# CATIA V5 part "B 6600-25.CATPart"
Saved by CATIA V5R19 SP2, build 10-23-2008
Part number: B 6600-25
Bounding box of the stored display mesh (mm): x -59.975 to 59.975, y -59.975 to 59.975, z 0 to 190
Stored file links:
  C:\Users\Bora\Desktop\3D Katı model\B serisi\B 6600\B 6600-25.CATPart
  C:\Program Files\Dassault Systemes\B19\intel_a\reffiles\standard\MetricThickPitch.txt
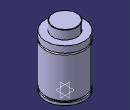
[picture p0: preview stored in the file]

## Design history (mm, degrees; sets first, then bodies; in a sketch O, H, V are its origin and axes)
Body1 (main body)
  Sketch1 on yz-plane, origin (0, 0, 0), H (0, 1, 0), V (0, 0, 1)
    point P3 (37.5, 189)
    point P5 (37.5, 189)
    point P10 (60, 137)
    point P11 (60, 142)
    point P13 (60, 142)
    point P14 (60, 137)
    line L1 (60, 0) -> (60, 8)
    line L2 (37.5, 189) -> (37.5, 162)
    arc A1 centre (36.5, 189) radius 1 from (37.5, 189) to (36.5, 190) ccw
    line L3 (56, 13) -> (56, 8)
    line L4 (60, 13) -> (60, 137)
    line L5 (60, 142) -> (60, 162)
    arc A2 centre (60, 139.5) radius 2.5 from (60, 142) to (60, 137) ccw
    line L6 (36.5, 190) -> (0, 190)
    point P15 (0, 190)
    line L7 (37.5, 162) -> (60, 162)
    line L8 (0, 0) -> (60, 0)
    line L9 (56, 13) -> (60, 13)
    line L10 (56, 8) -> (60, 8)
    coincidence: P15 V, P3 P5, P10 P14, P11 P13
    tangency: L6 A1
    horizontal: L7 H, L8 H, L9 H, L10 H
  Shaft1: profile Sketch1, axis Sketch1.V, angle 360
  Sketch2 on face of Shaft1 from Sketch1.L8, origin (0, 0, 0), H (1, 0, 0), V (0, -1, 0)
    point P1 (40, 0)
    distance P1 V = 40
  Hole1: placed by Sketch2, at (40, 0, 0) direction (0, 0, 1), diameter 8.376, depth 16, threaded "M10", thread diameter 10, thread depth 16, pitch 1.5
  CircPattern1: of Hole1, instances 4, angular step 90, axis from xy-plane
